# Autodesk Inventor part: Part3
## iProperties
Shininess: 77.0
Angle Display Precision: 2
Document Length Units: 11269
Document Angle Units: 11279
Document Time Units: 11290
Document Mass Units: 11283
Document Length Units Precision: 3
Document Angle Units Precision: 2
Compacted: True
Created: 2001-12
Part Number: Part3
Document SubType Name: Modeling
Designer: Renu Muthoo
Density: 1 g/cm^3
Density: 0.0
Volumn: 0.0
Area: 0.0
PropertySet Name: Model Information
Control State: 0
Master: False
Checked Out: False
Author: Renu Muthoo
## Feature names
1. Revolution2
2. Extrusion1
3. Circular Pattern2
